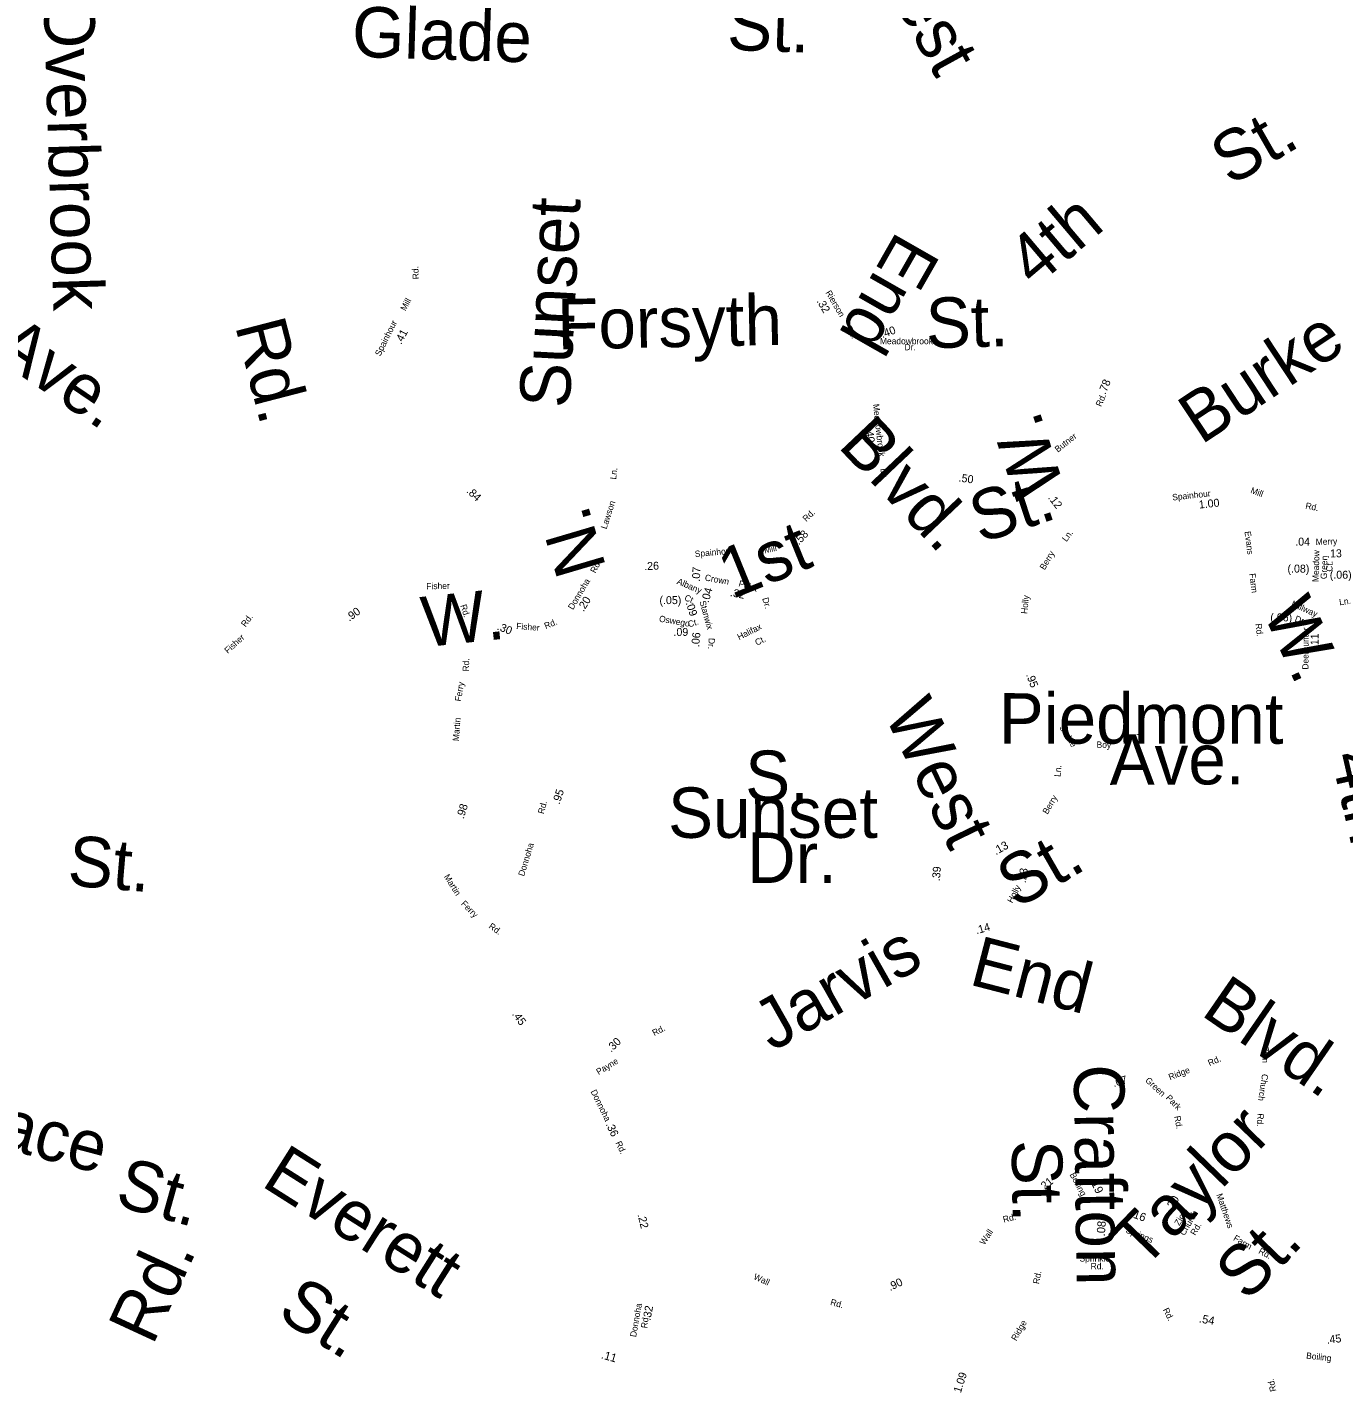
# Model space of a CAD drawing. Extents: x 1553981 to 1780076, y 812965 to 996873.
# Drawn here: x 1625598 to 1628079, y 853651 to 856224 of the extents above; entities that cross this region are included whole.
import ezdxf

# ---------------------------------------------------------------- set-up
doc = ezdxf.new("R2010")
doc.units = 0
for name, color, linetype in [('Exist Road Non-System Type 51 Label', 7, 'Continuous'), ('Exist Road Primary NC Service Mileage Hundredths English Label', 7, 'Continuous'), ('Exist Road Secondary Mileage Hundredths English Label', 7, 'Continuous'), ('Map Preparation Border Antique Large Shape', 7, 'Continuous')]:
    doc.layers.add(name, color=color, linetype=linetype)

msp = doc.modelspace()

# ---------------------------------------------------------------- texts
at = {"layer": 'Exist Road Non-System Type 51 Label'}
for s, height, rotation, p in [('West', 95, 298.7866, (1627172.5, 856379.4)), ('Overbrook', 95, 271.7966, (1625629.1, 856281.8)), ('St.', 95, 357.9009, (1626916.1, 856181.7)), ('Glade', 95, 358.1493, (1626209.1, 856168.6)), ('St.', 95, 29.7378, (1627865, 855924.1)), ('Sunset', 95, 87.0056, (1626620.2, 855505.2)), ('4th', 95, 40.2217, (1627496.8, 855731.6)), ('End', 95, 240.2776, (1627237.9, 855842.5)), ('Forsyth', 95, 1.1988, (1626597.9, 855616.7)), ('St.', 95, 1.4767, (1627292.7, 855619)), ('Ave.', 95, 325.8345, (1625529, 855605.9)), ('Rd.', 95, 284.5174, (1625989.6, 855662)), ('Burke', 95, 33.4252, (1627810.3, 855436.2)), ('Blvd.', 95, 313.5283, (1627124, 855434)), ('W.', 95, 108.2975, (1627553, 855358.1)), ('Ln.', 11.88, 83.8374, (1626708, 855371.4)), ('St.', 95, 18.2626, (1627394, 855250.9)), ('Lawson', 11.88, 71.9836, (1626689.8, 855277.4)), ('N.', 95, 106.4697, (1626689.6, 855206.1)), ('1st', 95, 22.1103, (1626925.8, 855145.5)), ('Evans', 11.88, 277.2971, (1627892, 855273.6)), ('Farm', 11.88, 277.0505, (1627901.1, 855194.2)), ('W.', 95, 6.1009, (1626346.7, 855055.6)), ('W.', 95, 294.6642, (1627925.8, 855122)), ('Rd.', 11.88, 277.0505, (1627912.5, 855099.7)), ('West', 95, 295.7859, (1627212.1, 854929.8)), ('Piedmont', 95, 359.962, (1627428.9, 854874.1)), ('Stable', 11.88, 302.3793, (1627542.7, 854904)), ('Ln.', 11.88, 82.3584, (1627700, 854888)), ('Ave.', 95, 0.2661, (1627638.1, 854796.3)), ('Boy', 11.88, 358.2179, (1627613.2, 854866.3)), ('4th', 95, 282.9625, (1628054.6, 854850.7)), ('St.', 95, 355.2042, (1625672.5, 854607)), ('St.', 95, 29.9304, (1627462.2, 854561.5)), ('Jarvis', 95, 29.4868, (1627002, 854292.7)), ('End', 95, 345.4593, (1627370.7, 854420.6)), ('Blvd.', 95, 325.3875, (1627807.7, 854363.7)), ('Zion', 11.88, 268.3275, (1627926.2, 854303.2)), ('Terrace', 95, 345.2394, (1625311.7, 854174.5)), ('Crafton', 95, 270.7497, (1627570.3, 854269)), ('Green', 11.88, 317.0669, (1627704, 854237.9)), ('Church', 11.87, 261.3324, (1627925.2, 854252.1)), ('Park', 11.88, 314.283, (1627742.9, 854205.6)), ('Taylor', 95, 45.9713, (1627701.5, 853880.9)), ('Rd.', 11.88, 280.6054, (1627759.4, 854171.4)), ('Rd.', 11.88, 267.718, (1627916.6, 854177.3)), ('Everett', 95, 327.6689, (1626036.9, 854041.9)), ('St.', 95, 270.7497, (1627453.4, 854126.6)), ('St.', 95, 344.3628, (1625761, 854004.5)), ('Matthews', 11.88, 289.1137, (1627838.7, 854023.7)), ('St.', 95, 45.9713, (1627897.4, 853820.4)), ('Farm', 11.88, 329.5037, (1627869.8, 853938.6)), ('Rd.', 95, 65.198, (1625834.6, 853738.1)), ('Rd.', 11.88, 331.6817, (1627917.2, 853914)), ('St.', 95, 327.6689, (1626066.4, 853794.3))]:
    msp.add_text(s, height=height, rotation=rotation, dxfattribs=at).set_placement(p)
for s, p in [('S.', (1626951.2, 854765.9)), ('Sunset', (1626805.8, 854696.4)), ('Dr.', (1626954.6, 854611.5))]:
    msp.add_text(s, height=95, dxfattribs=at).set_placement(p)
at = {"layer": 'Exist Road Primary NC Service Mileage Hundredths English Label'}
msp.add_text('.11', height=15.62, rotation=344.178, dxfattribs=at).set_placement((1626678.7, 853715.6))
at = {"layer": 'Exist Road Secondary Mileage Hundredths English Label'}
for s, height, rotation, p in [('.32', 15, 300.2424, (1627085.2, 855708)), ('.41', 15, 62.0284, (1626303, 855625.3)), ('.40', 15, 19.1321, (1627209.8, 855638.3)), ('.78', 15, 67.6488, (1627629.8, 855531)), ('.40', 15, 276.5324, (1627177.6, 855468.1)), ('.50', 15, 351.9064, (1627352.6, 855368.1)), ('.84', 15, 317.069, (1626424.8, 855348.4)), ('.12', 15, 307.4561, (1627521.1, 855337.1)), ('1.00', 15, 6.0898, (1627806.7, 855316.9)), ('.58', 15, 47.0142, (1627052.4, 855247.4)), ('.04', 15, 359.9567, (1627987.6, 855247.2)), ('.26', 15, 2.2863, (1626761.1, 855200.9)), ('.13', 15, 1.236, (1628047.7, 855224.7)), ('.07', 15, 86.7754, (1626865.6, 855178.9)), ('(.08)', 15, 359.7365, (1627973, 855196.4)), ('(.06)', 15, 359.7365, (1628052.7, 855184.9)), ('.04', 15, 73.8653, (1626882.2, 855138.7)), ('.32', 15, 348.3043, (1626921.9, 855152.3)), ('.20', 15, 58.4189, (1626646.6, 855121.7)), ('(.05)', 15, 0.0323, (1626789.6, 855136.9)), ('.09', 15, 287.7091, (1626838.9, 855139.3)), ('.90', 15, 35.7711, (1626205.1, 855103.7)), ('(.06)', 15, 359.7365, (1627940.6, 855104.5)), ('.30', 15, 338.2561, (1626482.5, 855089.2)), ('.09', 15, 0.1365, (1626816, 855076.9)), ('.06', 15, 84.4987, (1626864.3, 855055.3)), ('.11', 15, 89.4907, (1628031.6, 855053.9)), ('.95', 15, 291.093, (1627480, 855003.8)), ('.95', 15, 71.7577, (1626601.4, 854758.7)), ('.98', 15, 72.6558, (1626420.6, 854731.3)), ('.13', 15.62, 29.3063, (1627423.6, 854663.6)), ('.39', 15, 85.3728, (1627317.9, 854614.3)), ('.23', 15, 81.6818, (1627479.9, 854610.8)), ('.14', 15, 16.1225, (1627387.3, 854514.6)), ('.45', 15, 305.7799, (1626511.1, 854364)), ('.30', 15, 44.074, (1626698.6, 854291.5)), ('.67', 15, 16.3987, (1627645.7, 854226.6)), ('.36', 15, 295.2803, (1626688, 854156.7)), ('.21', 15, 38.7298, (1627511.3, 854029)), ('.19', 15.62, 295.671, (1627600.4, 854050.4)), ('.20', 15.62, 59.9005, (1627755.3, 853991.4)), ('.22', 15, 283.7493, (1626748.3, 853986)), ('.16', 15.62, 339.9515, (1627675.7, 853982.7)), ('.08', 15.62, 85.7635, (1627628.7, 853945)), ('.90', 15, 25.1598, (1627224.3, 853842.3)), ('.32', 15, 79.1388, (1626772.5, 853786)), ('.54', 15.62, 349.4949, (1627805.6, 853783.4)), ('.45', 15, 7.0371, (1628047.5, 853742.7)), ('1.09', 15, 72.11, (1627357.4, 853649.3))]:
    msp.add_text(s, height=height, rotation=rotation, dxfattribs=at).set_placement(p)
at = {"layer": 'Map Preparation Border Antique Large Shape'}
for s, height, rotation, p in [('Rd.', 11.88, 93.4516, (1626336.5, 855749.4)), ('Mill', 11.88, 62.0719, (1626311.2, 855688.4)), ('Rierson', 11.88, 300.2424, (1627102, 855723.9)), ('Spainhour', 11.88, 63.66, (1626263.5, 855603.2)), ('Rd.', 11.88, 302.0555, (1627140, 855656.9)), ('Rd.', 11.88, 65.9802, (1627621.8, 855508)), ('Meadowbrook', 11.875, 276.5324, (1627191.8, 855513.5)), ('Butner', 11.88, 38.2167, (1627540.3, 855422.2)), ('Dr.', 11.88, 277.6158, (1627205.9, 855392)), ('Spainhour', 11.88, 6.1076, (1627756.5, 855332.2)), ('Mill', 11.88, 339.6851, (1627902.4, 855346.6)), ('Rd.', 11.88, 348.5019, (1628006.1, 855317.1)), ('Rd.', 11.88, 43.1898, (1627066, 855291.4)), ('Ln.', 11.88, 53.4439, (1627556.5, 855253.5)), ('Spainhour', 11.88, 5.16, (1626856.8, 855225.5)), ('Mill', 11.87, 12.4162, (1626988.2, 855232.4)), ('Merry', 11.87, 1.6982, (1628026.4, 855248.4)), ('Rd.', 11.88, 61.8871, (1626668.8, 855194.2)), ('Berry', 11.88, 59.3405, (1627515.5, 855200.2)), ('Meadow', 11.87, 88.1716, (1628031.5, 855178.4)), ('Green', 11.87, 88.1716, (1628047.1, 855183.8)), ('Ct.', 11.87, 88.1716, (1628057.6, 855197.9)), ('Crown', 11.88, 350.0655, (1626874.5, 855181.4)), ('Fisher', 11.88, 0.9547, (1626350.4, 855164.8)), ('Donnoha', 11.88, 59.2945, (1626626.6, 855125.2)), ('Albany', 11.88, 336.6097, (1626821.4, 855175.5)), ('Point', 11.88, 343.2551, (1626937.7, 855170.8)), ('Ct.', 11.88, 336.6097, (1626835.5, 855144.7)), ('Stanwix', 11.87, 285.4808, (1626864.9, 855141.5)), ('Dr.', 11.87, 286.4141, (1626983.1, 855147.5)), ('Holly', 11.87, 84.0767, (1627482.6, 855118)), ('Millway', 11.87, 335.9208, (1627979, 855133.4)), ('Ln.', 11.87, 8.512, (1628071.3, 855134.5)), ('Rd.', 11.88, 53.663, (1626009.6, 855092.9)), ('Rd.', 11.88, 287.6002, (1626414.3, 855134.3)), ('Oswego', 11.88, 350.2769, (1626788.2, 855104)), ('Dr.', 11.87, 339.8966, (1627985.8, 855104.8)), ('Fisher', 11.87, 355.4883, (1626519.4, 855090)), ('Rd.', 11.87, 22.0481, (1626575.4, 855089.7)), ('Ct.', 11.87, 16.5782, (1626845.1, 855092.9)), ('Halifax', 11.88, 26.6319, (1626939.9, 855068.7)), ('Deerhunter', 11.87, 89.7137, (1628012.6, 855013.4)), ('Fisher', 11.88, 42.0403, (1625976.3, 855042.9)), ('Dr.', 11.88, 266.6288, (1626882.4, 855073.4)), ('Ct.', 11.88, 26.6319, (1626973.2, 855058.3)), ('Rd.', 11.88, 89.0879, (1626430.7, 855009.9)), ('Ferry', 11.87, 80.5895, (1626415.5, 854952.8)), ('Martin', 11.88, 85.5597, (1626411.5, 854878.4)), ('Ln.', 11.88, 85.2954, (1627545.4, 854811)), ('Rd.', 11.88, 75.3835, (1626571.7, 854740.6)), ('Berry', 11.88, 59.7199, (1627520.9, 854739.8)), ('Donnoha', 11.87, 73.0648, (1626534.4, 854623.2)), ('Martin', 11.88, 302.0604, (1626383, 854623.4)), ('Holly', 11.87, 62.6982, (1627454.6, 854572.5)), ('Ferry', 11.88, 315.0868, (1626414.7, 854571)), ('Rd.', 11.87, 324.7414, (1626466.7, 854527.3)), ('Rd.', 11.88, 26.9837, (1626779.8, 854322.7)), ('Payne', 11.88, 31.1417, (1626674.9, 854249.2)), ('Rd.', 11.88, 23.3325, (1627826.2, 854266)), ('Ridge', 11.88, 20.9745, (1627751.6, 854239.5)), ('Donnoha', 11.88, 296.1767, (1626659.5, 854218.4)), ('Rd.', 11.88, 295.3654, (1626706.4, 854121.5)), ('Boiling', 11.88, 298.2036, (1627562.1, 854061.8)), ('Rd.', 11.88, 13.8042, (1627438.4, 853971.2)), ('Zion', 11.88, 59.3418, (1627769.2, 853964.5)), ('Church', 11.88, 59.3418, (1627779, 853945.8)), ('Wall', 11.88, 56.2705, (1627401.9, 853928.1)), ('Springs', 11.88, 337.982, (1627667.2, 853952.8)), ('Rd.', 11.87, 60.4474, (1627799.4, 853946.1)), ('Sprinkle', 11.88, 0.0236, (1627581.2, 853897.9)), ('Rd.', 11.87, 78.8746, (1627504.7, 853854.8)), ('Rd.', 11.88, 359.7887, (1627602.1, 853883.5)), ('Wall', 11.88, 334.9332, (1626965.8, 853865.3)), ('Rd.', 11.88, 344.1462, (1627110.6, 853816.4)), ('Donnoha', 11.88, 79.9475, (1626745.5, 853754.8)), ('Rd.', 11.87, 296.8507, (1627737.9, 853807)), ('Rd.', 11.87, 82.1437, (1626766.3, 853771.6)), ('Ridge', 11.88, 60.0729, (1627461.8, 853747.3)), ('Boiling', 11.87, 353.8947, (1628007.8, 853715)), ('Rd.', 11.88, 102.3482, (1627952.1, 853654.1))]:
    msp.add_text(s, height=height, rotation=rotation, dxfattribs=at).set_placement(p)
for s, height, p in [('Meadowbrook', 11.875, (1627205.1, 855626.7)), ('Dr.', 11.88, (1627251.4, 855615.4))]:
    msp.add_text(s, height=height, dxfattribs=at).set_placement(p)

doc.saveas('drawing.dxf')
